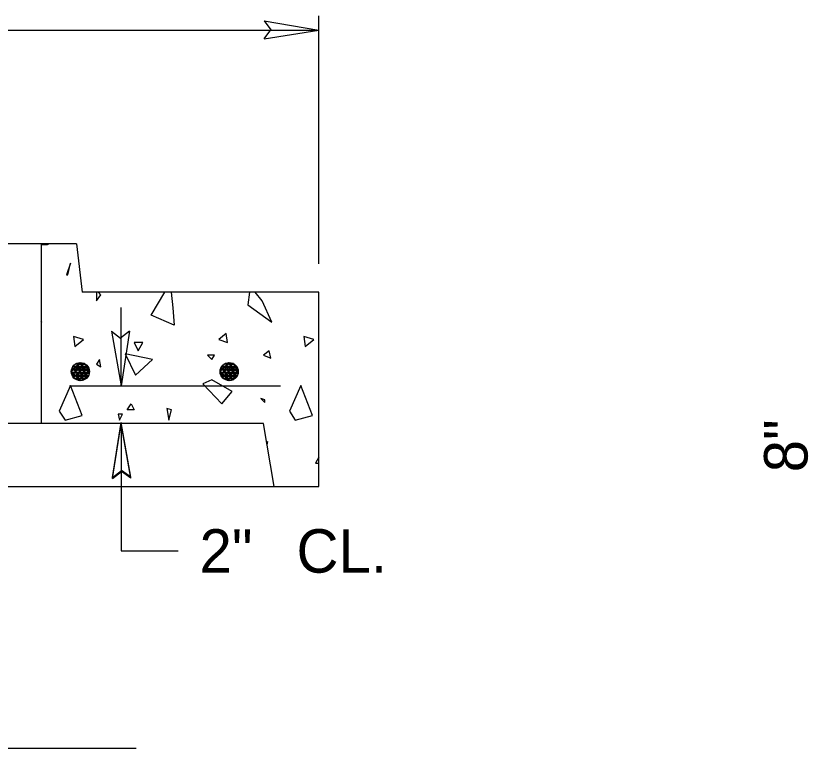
# Model space of a CAD drawing. Extents: x 26.41 to 33.74, y 20.66 to 30.6.
# Drawn here: x 30.528 to 31.62, y 27.311 to 28.321 of the extents above; entities that cross this region are included whole.
import ezdxf

# ---------------------------------------------------------------- set-up
doc = ezdxf.new("R2010")
doc.units = 0
for name, color, linetype in [('DETL-DIMS', 7, 'Continuous'), ('DETL-LINE', 7, 'Continuous'), ('DETL-NOTE', 7, 'Continuous'), ('DETL-PATT', 7, 'Continuous'), ('DETL-TITL', 7, 'Continuous')]:
    doc.layers.add(name, color=color, linetype=linetype)

msp = doc.modelspace()

# ---------------------------------------------------------------- linework, layer by layer
at = {"layer": 'DETL-DIMS'}
for p, q in [((30.8701, 28.3146), (30.9456, 28.3017)), ((30.8701, 28.3146), (30.8795, 28.302)), ((30.9456, 27.9792), (30.9456, 28.3214)), ((29.3909, 28.3017), (30.9456, 28.3017)), ((30.87, 28.2894), (30.8795, 28.302)), ((30.87, 28.2894), (30.9456, 28.3017)), ((30.6731, 27.8108), (30.6731, 27.9189)), ((30.6594, 27.8861), (30.6731, 27.8108)), ((30.6594, 27.8861), (30.6721, 27.8768)), ((30.6846, 27.8864), (30.6721, 27.8768)), ((30.6846, 27.8864), (30.6731, 27.8108)), ((30.6611, 27.6845), (30.6729, 27.7601)), ((30.6611, 27.6832), (30.6729, 27.7588)), ((30.6863, 27.6847), (30.6729, 27.7601)), ((30.6729, 27.7601), (30.6729, 27.5831)), ((30.6863, 27.6835), (30.6729, 27.7588)), ((30.6611, 27.6845), (30.6736, 27.694)), ((30.6611, 27.6832), (30.6736, 27.6928)), ((30.6863, 27.6847), (30.6736, 27.694)), ((30.6863, 27.6835), (30.6736, 27.6928)), ((30.6729, 27.5831), (30.7515, 27.5831))]:
    msp.add_line(p, q, dxfattribs=at)
at = {"layer": 'DETL-LINE'}
for p, q in [((30.6113, 28.0069), (29.4803, 28.0069)), ((30.5628, 28.0069), (30.5628, 27.7588)), ((30.6113, 28.0069), (30.6193, 27.9399)), ((30.9456, 27.9399), (30.6193, 27.9399)), ((30.9456, 27.6721), (30.9456, 27.9399)), ((30.606, 27.8351), (30.6151, 27.8255)), ((30.6157, 27.8365), (30.6062, 27.8273)), ((30.6158, 27.8423), (30.6063, 27.8332)), ((30.6163, 27.8421), (30.6067, 27.8329)), ((30.6162, 27.8362), (30.6067, 27.827)), ((30.6206, 27.8363), (30.6073, 27.8365)), ((30.6205, 27.8333), (30.6073, 27.8336)), ((30.6206, 27.8375), (30.6074, 27.8377)), ((30.6089, 27.8379), (30.6181, 27.8284)), ((30.6186, 27.8336), (30.6091, 27.8244)), ((30.6187, 27.8394), (30.6092, 27.8302)), ((30.6192, 27.8391), (30.6096, 27.8299)), ((30.6247, 27.8333), (30.6114, 27.8335)), ((30.6247, 27.8374), (30.6115, 27.8376)), ((30.6247, 27.8362), (30.6115, 27.8364)), ((30.6118, 27.8349), (30.621, 27.8254)), ((30.6119, 27.8408), (30.621, 27.8313)), ((30.6216, 27.8364), (30.612, 27.8272)), ((30.622, 27.8361), (30.6124, 27.8269)), ((30.6147, 27.8378), (30.6239, 27.8283)), ((30.6244, 27.8335), (30.6149, 27.8243)), ((30.6245, 27.8393), (30.615, 27.8301)), ((30.625, 27.839), (30.6154, 27.8298)), ((30.6288, 27.8332), (30.6155, 27.8334)), ((30.6176, 27.8349), (30.6268, 27.8253)), ((30.6177, 27.8406), (30.6269, 27.8311)), ((30.6274, 27.8363), (30.6179, 27.8271)), ((30.6278, 27.836), (30.6183, 27.8268)), ((30.8111, 27.8351), (30.8203, 27.8255)), ((30.8209, 27.8365), (30.8114, 27.8273)), ((30.821, 27.8423), (30.8115, 27.8332)), ((30.8214, 27.8362), (30.8118, 27.827)), ((30.8215, 27.8421), (30.8119, 27.8329)), ((30.8258, 27.8375), (30.8125, 27.8377)), ((30.8258, 27.8363), (30.8125, 27.8365)), ((30.8257, 27.8333), (30.8125, 27.8336)), ((30.8141, 27.8379), (30.8233, 27.8284)), ((30.8238, 27.8336), (30.8142, 27.8244)), ((30.8239, 27.8394), (30.8144, 27.8302)), ((30.8243, 27.8391), (30.8148, 27.8299)), ((30.8299, 27.8362), (30.8166, 27.8364)), ((30.8298, 27.8333), (30.8166, 27.8335)), ((30.8299, 27.8374), (30.8167, 27.8376)), ((30.8169, 27.8349), (30.8261, 27.8254)), ((30.8171, 27.8408), (30.8262, 27.8313)), ((30.8267, 27.8364), (30.8172, 27.8272)), ((30.8272, 27.8361), (30.8176, 27.8269)), ((30.8199, 27.8378), (30.8291, 27.8283)), ((30.8296, 27.8335), (30.8201, 27.8243)), ((30.8297, 27.8393), (30.8202, 27.8301)), ((30.8302, 27.839), (30.8206, 27.8298)), ((30.834, 27.8332), (30.8207, 27.8334)), ((30.8228, 27.8349), (30.832, 27.8253)), ((30.8229, 27.8406), (30.8321, 27.8311)), ((30.8326, 27.8363), (30.823, 27.8271)), ((30.833, 27.836), (30.8235, 27.8268)), ((30.6058, 27.8292), (30.615, 27.8197)), ((30.6204, 27.8251), (30.6071, 27.8253)), ((30.6203, 27.8239), (30.6071, 27.8241)), ((30.6205, 27.8292), (30.6072, 27.8294)), ((30.6204, 27.828), (30.6072, 27.8283)), ((30.6205, 27.8322), (30.6073, 27.8324)), ((30.6088, 27.8321), (30.618, 27.8225)), ((30.619, 27.8333), (30.6095, 27.8241)), ((30.6245, 27.8238), (30.6112, 27.8241)), ((30.6246, 27.8291), (30.6113, 27.8294)), ((30.6245, 27.828), (30.6113, 27.8282)), ((30.6245, 27.825), (30.6113, 27.8252)), ((30.6246, 27.8321), (30.6114, 27.8323)), ((30.6117, 27.8291), (30.6209, 27.8196)), ((30.6215, 27.8306), (30.6119, 27.8214)), ((30.6219, 27.8303), (30.6124, 27.8211)), ((30.6146, 27.832), (30.6238, 27.8224)), ((30.6244, 27.8276), (30.6148, 27.8184)), ((30.6247, 27.8273), (30.6152, 27.8181)), ((30.6249, 27.8331), (30.6153, 27.8239)), ((30.6287, 27.8279), (30.6154, 27.8281)), ((30.6288, 27.832), (30.6155, 27.8322)), ((30.6287, 27.8291), (30.6155, 27.8293)), ((30.6273, 27.8305), (30.6177, 27.8213)), ((30.6277, 27.8302), (30.6182, 27.821)), ((30.811, 27.8292), (30.8202, 27.8197)), ((30.8256, 27.828), (30.8123, 27.8283)), ((30.8256, 27.8251), (30.8123, 27.8253)), ((30.8255, 27.8239), (30.8123, 27.8241)), ((30.8257, 27.8322), (30.8124, 27.8324)), ((30.8256, 27.8292), (30.8124, 27.8294)), ((30.814, 27.8321), (30.8232, 27.8225)), ((30.8242, 27.8333), (30.8147, 27.8241)), ((30.8297, 27.825), (30.8164, 27.8252)), ((30.8296, 27.8238), (30.8164, 27.8241)), ((30.8298, 27.8291), (30.8165, 27.8294)), ((30.8297, 27.828), (30.8165, 27.8282)), ((30.8298, 27.8321), (30.8166, 27.8323)), ((30.8168, 27.8291), (30.826, 27.8196)), ((30.8267, 27.8306), (30.8171, 27.8214)), ((30.8271, 27.8303), (30.8175, 27.8211)), ((30.8198, 27.832), (30.829, 27.8224)), ((30.8295, 27.8276), (30.82, 27.8184)), ((30.8299, 27.8273), (30.8204, 27.8181)), ((30.83, 27.8331), (30.8205, 27.8239)), ((30.8339, 27.8291), (30.8206, 27.8293)), ((30.8338, 27.8279), (30.8206, 27.8281)), ((30.8339, 27.832), (30.8207, 27.8322)), ((30.8325, 27.8305), (30.8229, 27.8213)), ((30.8329, 27.8302), (30.8234, 27.821)), ((30.6244, 27.8209), (30.6112, 27.8211)), ((30.8296, 27.8209), (30.8164, 27.8211)), ((30.6019, 27.8108), (30.8927, 27.8108)), ((30.8691, 27.7588), (29.4662, 27.7588)), ((30.884, 27.6721), (30.8691, 27.7588)), ((29.3909, 27.6721), (30.9456, 27.6721))]:
    msp.add_line(p, q, dxfattribs=at)
for points in [[(30.6133, 27.8392), (30.6042, 27.8305)], [(30.6103, 27.8363), (30.6042, 27.8305)], [(30.6074, 27.8335), (30.6042, 27.8305)], [(30.6129, 27.8395), (30.6043, 27.8312)], [(30.6099, 27.8366), (30.6043, 27.8312)], [(30.6069, 27.8338), (30.6043, 27.8312)], [(30.6164, 27.8334), (30.6047, 27.8336)], [(30.6123, 27.8335), (30.6047, 27.8336)], [(30.6082, 27.8335), (30.6047, 27.8336)], [(30.6128, 27.8337), (30.605, 27.8262)], [(30.6132, 27.8333), (30.6052, 27.8257)], [(30.6054, 27.8357), (30.6122, 27.8285)], [(30.6164, 27.8364), (30.6058, 27.8366)], [(30.6123, 27.8364), (30.6058, 27.8366)], [(30.6082, 27.8365), (30.6058, 27.8366)], [(30.6165, 27.8375), (30.6065, 27.8377)], [(30.6124, 27.8376), (30.6065, 27.8377)], [(30.6082, 27.8377), (30.6065, 27.8377)], [(30.6077, 27.8391), (30.6152, 27.8314)], [(30.6164, 27.8429), (30.6093, 27.836)], [(30.6207, 27.8404), (30.6095, 27.8406)], [(30.6165, 27.8405), (30.6095, 27.8406)], [(30.6124, 27.8406), (30.6095, 27.8406)], [(30.6172, 27.8429), (30.6097, 27.8357)], [(30.6111, 27.8416), (30.6182, 27.8342)], [(30.6207, 27.8416), (30.6113, 27.8417)], [(30.6166, 27.8416), (30.6113, 27.8417)], [(30.6124, 27.8417), (30.6113, 27.8417)], [(30.6243, 27.8403), (30.6115, 27.8406)], [(30.6225, 27.8416), (30.6116, 27.8417)], [(30.6214, 27.842), (30.6122, 27.8331)], [(30.6164, 27.8429), (30.6123, 27.8389)], [(30.622, 27.8418), (30.6126, 27.8328)], [(30.6172, 27.8429), (30.6127, 27.8386)], [(30.6214, 27.842), (30.6152, 27.8359)], [(30.622, 27.8418), (30.6155, 27.8356)], [(30.6156, 27.8429), (30.6212, 27.8371)], [(30.6156, 27.8429), (30.624, 27.8341)], [(30.6271, 27.8373), (30.6156, 27.8375)], [(30.6278, 27.8361), (30.6156, 27.8364)], [(30.6225, 27.8416), (30.6157, 27.8417)], [(30.6243, 27.8403), (30.6157, 27.8405)], [(30.625, 27.8397), (30.618, 27.8329)], [(30.6254, 27.8394), (30.6184, 27.8327)], [(30.6278, 27.8361), (30.6197, 27.8363)], [(30.6289, 27.8332), (30.6197, 27.8333)], [(30.6225, 27.8416), (30.6198, 27.8416)], [(30.6243, 27.8403), (30.6198, 27.8404)], [(30.6271, 27.8373), (30.6198, 27.8375)], [(30.6206, 27.8377), (30.629, 27.8289)], [(30.6276, 27.8365), (30.6209, 27.83)], [(30.6278, 27.836), (30.6213, 27.8297)], [(30.6228, 27.8414), (30.6242, 27.8399)], [(30.6228, 27.8414), (30.627, 27.837)], [(30.6228, 27.8414), (30.6278, 27.8361)], [(30.6234, 27.8348), (30.629, 27.8289)], [(30.6236, 27.8406), (30.6278, 27.8361)], [(30.6264, 27.8376), (30.6278, 27.8361)], [(30.818, 27.8395), (30.8094, 27.8312)], [(30.8185, 27.8392), (30.8094, 27.8305)], [(30.8151, 27.8366), (30.8094, 27.8312)], [(30.8155, 27.8363), (30.8094, 27.8305)], [(30.8121, 27.8338), (30.8094, 27.8312)], [(30.8125, 27.8335), (30.8094, 27.8305)], [(30.8216, 27.8334), (30.8098, 27.8336)], [(30.8175, 27.8335), (30.8098, 27.8336)], [(30.8133, 27.8335), (30.8098, 27.8336)], [(30.8179, 27.8337), (30.8101, 27.8262)], [(30.8184, 27.8333), (30.8104, 27.8257)], [(30.8105, 27.8357), (30.8174, 27.8285)], [(30.8216, 27.8364), (30.811, 27.8366)], [(30.8175, 27.8364), (30.811, 27.8366)], [(30.8134, 27.8365), (30.811, 27.8366)], [(30.8217, 27.8375), (30.8117, 27.8377)], [(30.8175, 27.8376), (30.8117, 27.8377)], [(30.8134, 27.8377), (30.8117, 27.8377)], [(30.8129, 27.8391), (30.8204, 27.8314)], [(30.8216, 27.8429), (30.8145, 27.836)], [(30.8258, 27.8404), (30.8146, 27.8406)], [(30.8217, 27.8405), (30.8146, 27.8406)], [(30.8176, 27.8406), (30.8146, 27.8406)], [(30.8223, 27.8429), (30.8149, 27.8357)], [(30.8162, 27.8416), (30.8234, 27.8342)], [(30.8258, 27.8416), (30.8165, 27.8417)], [(30.8217, 27.8416), (30.8165, 27.8417)], [(30.8176, 27.8417), (30.8165, 27.8417)], [(30.8295, 27.8403), (30.8167, 27.8406)], [(30.8276, 27.8416), (30.8168, 27.8417)], [(30.8266, 27.842), (30.8173, 27.8331)], [(30.8216, 27.8429), (30.8175, 27.8389)], [(30.8271, 27.8418), (30.8177, 27.8328)], [(30.8223, 27.8429), (30.8179, 27.8386)], [(30.8266, 27.842), (30.8203, 27.8359)], [(30.8271, 27.8418), (30.8207, 27.8356)], [(30.8208, 27.8429), (30.8263, 27.8371)], [(30.8208, 27.8429), (30.8292, 27.8341)], [(30.8295, 27.8403), (30.8208, 27.8405)], [(30.8323, 27.8373), (30.8208, 27.8375)], [(30.833, 27.8361), (30.8208, 27.8364)], [(30.8276, 27.8416), (30.8209, 27.8417)], [(30.8302, 27.8397), (30.8232, 27.8329)], [(30.8306, 27.8394), (30.8236, 27.8327)], [(30.834, 27.8332), (30.8248, 27.8333)], [(30.8323, 27.8373), (30.8249, 27.8375)], [(30.833, 27.8361), (30.8249, 27.8363)], [(30.8276, 27.8416), (30.825, 27.8416)], [(30.8295, 27.8403), (30.825, 27.8404)], [(30.8258, 27.8377), (30.8342, 27.8289)], [(30.8328, 27.8365), (30.826, 27.83)], [(30.833, 27.836), (30.8265, 27.8297)], [(30.828, 27.8414), (30.8293, 27.8399)], [(30.828, 27.8414), (30.8322, 27.837)], [(30.828, 27.8414), (30.833, 27.8361)], [(30.8286, 27.8348), (30.8342, 27.8289)], [(30.8287, 27.8406), (30.833, 27.8361)], [(30.8316, 27.8376), (30.833, 27.8361)], [(30.6042, 27.8309), (30.6093, 27.8256)], [(30.6042, 27.8309), (30.6121, 27.8226)], [(30.6044, 27.8306), (30.6042, 27.8305)], [(30.6163, 27.8293), (30.6043, 27.8295)], [(30.6122, 27.8294), (30.6043, 27.8295)], [(30.6081, 27.8294), (30.6043, 27.8295)], [(30.6164, 27.8322), (30.6044, 27.8324)], [(30.6122, 27.8323), (30.6044, 27.8324)], [(30.6081, 27.8324), (30.6044, 27.8324)], [(30.6163, 27.8281), (30.6044, 27.8283)], [(30.6122, 27.8282), (30.6044, 27.8283)], [(30.608, 27.8283), (30.6044, 27.8283)], [(30.6098, 27.8308), (30.605, 27.8262)], [(30.6068, 27.828), (30.605, 27.8262)], [(30.6102, 27.8305), (30.6052, 27.8257)], [(30.6073, 27.8276), (30.6052, 27.8257)], [(30.6163, 27.8252), (30.6053, 27.8254)], [(30.6121, 27.8252), (30.6053, 27.8254)], [(30.608, 27.8253), (30.6053, 27.8254)], [(30.6162, 27.824), (30.606, 27.8242)], [(30.6121, 27.8241), (30.606, 27.8242)], [(30.608, 27.8241), (30.606, 27.8242)], [(30.6156, 27.8307), (30.6071, 27.8225)], [(30.6126, 27.8278), (30.6071, 27.8225)], [(30.6097, 27.825), (30.6071, 27.8225)], [(30.6161, 27.8304), (30.6074, 27.8221)], [(30.6131, 27.8276), (30.6074, 27.8221)], [(30.6101, 27.8247), (30.6074, 27.8221)], [(30.6087, 27.8263), (30.6166, 27.818)], [(30.6185, 27.8277), (30.6103, 27.8198)], [(30.6155, 27.8248), (30.6103, 27.8198)], [(30.6189, 27.8274), (30.6108, 27.8195)], [(30.6159, 27.8246), (30.6108, 27.8195)], [(30.6116, 27.8233), (30.6166, 27.818)], [(30.6145, 27.8261), (30.6214, 27.819)], [(30.6214, 27.8247), (30.6145, 27.8182)], [(30.6218, 27.8245), (30.6152, 27.8181)], [(30.6272, 27.8238), (30.6153, 27.824)], [(30.6278, 27.8249), (30.6154, 27.8252)], [(30.6174, 27.8232), (30.6214, 27.819)], [(30.6175, 27.829), (30.625, 27.8212)], [(30.6278, 27.8249), (30.6195, 27.8251)], [(30.6272, 27.8238), (30.6195, 27.8239)], [(30.6291, 27.832), (30.6196, 27.8322)], [(30.6291, 27.8291), (30.6196, 27.8292)], [(30.6289, 27.8279), (30.6196, 27.828)], [(30.6203, 27.826), (30.625, 27.8212)], [(30.6205, 27.8319), (30.6276, 27.8245)], [(30.629, 27.8321), (30.6207, 27.8242)], [(30.6282, 27.8256), (30.6211, 27.8188)], [(30.6272, 27.8246), (30.6211, 27.8188)], [(30.6291, 27.8315), (30.6212, 27.8239)], [(30.6275, 27.8242), (30.6225, 27.8195)], [(30.6275, 27.8242), (30.6225, 27.8195)], [(30.6232, 27.823), (30.625, 27.8212)], [(30.6233, 27.8289), (30.6276, 27.8245)], [(30.6282, 27.8256), (30.6236, 27.8212)], [(30.629, 27.8321), (30.6237, 27.827)], [(30.6275, 27.8242), (30.624, 27.8209)], [(30.6291, 27.8315), (30.6242, 27.8267)], [(30.6262, 27.8259), (30.6276, 27.8245)], [(30.6263, 27.8318), (30.629, 27.8289)], [(30.6282, 27.8256), (30.6266, 27.8241)], [(30.6275, 27.8242), (30.627, 27.8237)], [(30.8094, 27.8309), (30.8144, 27.8256)], [(30.8094, 27.8309), (30.8173, 27.8226)], [(30.8096, 27.8306), (30.8094, 27.8305)], [(30.8215, 27.8293), (30.8094, 27.8295)], [(30.8174, 27.8294), (30.8094, 27.8295)], [(30.8133, 27.8294), (30.8094, 27.8295)], [(30.8215, 27.8322), (30.8096, 27.8324)], [(30.8174, 27.8323), (30.8096, 27.8324)], [(30.8133, 27.8324), (30.8096, 27.8324)], [(30.8215, 27.8281), (30.8096, 27.8283)], [(30.8173, 27.8282), (30.8096, 27.8283)], [(30.8132, 27.8283), (30.8096, 27.8283)], [(30.8149, 27.8308), (30.8101, 27.8262)], [(30.812, 27.828), (30.8101, 27.8262)], [(30.8154, 27.8305), (30.8104, 27.8257)], [(30.8124, 27.8276), (30.8104, 27.8257)], [(30.8214, 27.8252), (30.8105, 27.8254)], [(30.8173, 27.8252), (30.8105, 27.8254)], [(30.8132, 27.8253), (30.8105, 27.8254)], [(30.8214, 27.824), (30.8111, 27.8242)], [(30.8173, 27.8241), (30.8111, 27.8242)], [(30.8131, 27.8241), (30.8111, 27.8242)], [(30.8208, 27.8307), (30.8123, 27.8225)], [(30.8178, 27.8278), (30.8123, 27.8225)], [(30.8149, 27.825), (30.8123, 27.8225)], [(30.8212, 27.8304), (30.8126, 27.8221)], [(30.8182, 27.8276), (30.8126, 27.8221)], [(30.8153, 27.8247), (30.8126, 27.8221)], [(30.8139, 27.8263), (30.8218, 27.818)], [(30.8237, 27.8277), (30.8155, 27.8198)], [(30.8207, 27.8248), (30.8155, 27.8198)], [(30.8241, 27.8274), (30.8159, 27.8195)], [(30.8211, 27.8246), (30.8159, 27.8195)], [(30.8168, 27.8233), (30.8218, 27.818)], [(30.8197, 27.8261), (30.8266, 27.819)], [(30.8265, 27.8247), (30.8197, 27.8182)], [(30.827, 27.8245), (30.8204, 27.8181)], [(30.8324, 27.8238), (30.8205, 27.824)], [(30.833, 27.8249), (30.8206, 27.8252)], [(30.8226, 27.829), (30.8302, 27.8212)], [(30.8226, 27.8232), (30.8266, 27.819)], [(30.834, 27.8279), (30.8247, 27.828)], [(30.833, 27.8249), (30.8247, 27.8251)], [(30.8324, 27.8238), (30.8247, 27.8239)], [(30.8342, 27.832), (30.8248, 27.8322)], [(30.8342, 27.8291), (30.8248, 27.8292)], [(30.8255, 27.826), (30.8302, 27.8212)], [(30.8256, 27.8319), (30.8328, 27.8245)], [(30.8342, 27.8321), (30.8259, 27.8242)], [(30.8343, 27.8315), (30.8263, 27.8239)], [(30.8333, 27.8256), (30.8263, 27.8188)], [(30.8324, 27.8246), (30.8263, 27.8188)], [(30.8327, 27.8242), (30.8277, 27.8195)], [(30.8327, 27.8242), (30.8277, 27.8195)], [(30.8284, 27.823), (30.8302, 27.8212)], [(30.8285, 27.8289), (30.8328, 27.8245)], [(30.8333, 27.8256), (30.8288, 27.8212)], [(30.8342, 27.8321), (30.8289, 27.827)], [(30.8327, 27.8242), (30.8292, 27.8209)], [(30.8343, 27.8315), (30.8293, 27.8267)], [(30.8314, 27.8259), (30.8328, 27.8245)], [(30.8315, 27.8318), (30.8342, 27.8289)], [(30.8333, 27.8256), (30.8318, 27.8241)], [(30.8327, 27.8242), (30.8322, 27.8237)], [(30.6203, 27.821), (30.6084, 27.8212)], [(30.6162, 27.821), (30.6084, 27.8212)], [(30.612, 27.8211), (30.6084, 27.8212)], [(30.6203, 27.8198), (30.61, 27.82)], [(30.6161, 27.8199), (30.61, 27.82)], [(30.612, 27.8199), (30.61, 27.82)], [(30.6125, 27.822), (30.6103, 27.8198)], [(30.613, 27.8217), (30.6108, 27.8195)], [(30.623, 27.8197), (30.6111, 27.8199)], [(30.6144, 27.8203), (30.6166, 27.818)], [(30.6184, 27.8219), (30.6145, 27.8182)], [(30.6154, 27.819), (30.6145, 27.8182)], [(30.6188, 27.8216), (30.6152, 27.8181)], [(30.6159, 27.8187), (30.6152, 27.8181)], [(30.6246, 27.8209), (30.6153, 27.821)], [(30.623, 27.8197), (30.6153, 27.8199)], [(30.6246, 27.8209), (30.6194, 27.821)], [(30.623, 27.8197), (30.6194, 27.8198)], [(30.6203, 27.8202), (30.6214, 27.819)], [(30.6242, 27.8218), (30.6211, 27.8188)], [(30.6212, 27.8189), (30.6211, 27.8188)], [(30.6246, 27.8215), (30.6225, 27.8195)], [(30.8255, 27.821), (30.8136, 27.8212)], [(30.8214, 27.821), (30.8136, 27.8212)], [(30.8172, 27.8211), (30.8136, 27.8212)], [(30.8254, 27.8198), (30.8152, 27.82)], [(30.8213, 27.8199), (30.8152, 27.82)], [(30.8172, 27.8199), (30.8152, 27.82)], [(30.8177, 27.822), (30.8155, 27.8198)], [(30.8182, 27.8217), (30.8159, 27.8195)], [(30.8281, 27.8197), (30.8163, 27.8199)], [(30.8196, 27.8203), (30.8218, 27.818)], [(30.8236, 27.8219), (30.8197, 27.8182)], [(30.8206, 27.819), (30.8197, 27.8182)], [(30.824, 27.8216), (30.8204, 27.8181)], [(30.8281, 27.8197), (30.8204, 27.8199)], [(30.821, 27.8187), (30.8204, 27.8181)], [(30.8298, 27.8209), (30.8205, 27.821)], [(30.8298, 27.8209), (30.8246, 27.821)], [(30.8281, 27.8197), (30.8246, 27.8198)], [(30.8254, 27.8202), (30.8266, 27.819)], [(30.8294, 27.8218), (30.8263, 27.8188)], [(30.8264, 27.8189), (30.8263, 27.8188)], [(30.8298, 27.8215), (30.8277, 27.8195)]]:
    msp.add_lwpolyline(points, dxfattribs=at)
for centre in [(30.6167, 27.8305), (30.8219, 27.8305)]:
    msp.add_circle(centre, 0.0125, dxfattribs=at)
at = {"layer": 'DETL-PATT'}
for points in [[(30.5628, 28.0057), (30.5715, 28.0057), (30.5731, 28.0069)], [(30.639, 27.9399), (30.639, 27.9283), (30.6451, 27.9363), (30.6415, 27.9399)], [(30.7418, 27.9399), (30.7442, 27.9184), (30.746, 27.8948), (30.7144, 27.9085), (30.733, 27.9399)], [(30.85, 27.9399), (30.8474, 27.9226), (30.8809, 27.8986), (30.8673, 27.9283), (30.8579, 27.9399)], [(30.5628, 27.8991), (30.5635, 27.8986), (30.5628, 27.9001)], [(30.8742, 27.7294), (30.8753, 27.734), (30.8737, 27.7325)], [(30.9456, 27.7125), (30.9408, 27.7043), (30.9456, 27.7043)]]:
    msp.add_lwpolyline(points, dxfattribs=at)
for points in [[(30.5975, 27.9641), (30.5994, 27.9641), (30.6031, 27.9802)], [(30.6074, 27.8788), (30.6093, 27.8651), (30.621, 27.875)], [(30.8177, 27.883), (30.8078, 27.875), (30.8196, 27.8708)], [(30.9248, 27.8788), (30.9267, 27.8651), (30.9385, 27.875)], [(30.6909, 27.8708), (30.6965, 27.859), (30.7026, 27.8708)], [(30.6786, 27.8552), (30.6927, 27.8255), (30.7163, 27.8472)], [(30.8691, 27.8533), (30.8791, 27.8491), (30.8772, 27.859)], [(30.639, 27.841), (30.6451, 27.8373), (30.6432, 27.8472)], [(30.7918, 27.8533), (30.7979, 27.8472), (30.8017, 27.8533)], [(30.7857, 27.8137), (30.8116, 27.7859), (30.8258, 27.8033), (30.7979, 27.8193)], [(30.5956, 27.7637), (30.6192, 27.7698), (30.6031, 27.8113), (30.5876, 27.776)], [(30.913, 27.7637), (30.9366, 27.7698), (30.9206, 27.8113), (30.905, 27.776)], [(30.871, 27.7915), (30.8654, 27.7934), (30.871, 27.7877)], [(30.6866, 27.7859), (30.6909, 27.7778), (30.681, 27.7778)], [(30.7361, 27.7797), (30.7385, 27.7637), (30.7423, 27.7778)], [(30.6687, 27.7717), (30.6706, 27.7637), (30.6748, 27.7717)]]:
    msp.add_lwpolyline(points, close=True, dxfattribs=at)
at = {"layer": 'DETL-TITL'}
msp.add_line((29.6428, 27.311), (30.6936, 27.311), dxfattribs=at)

# ---------------------------------------------------------------- texts
at = {"layer": 'DETL-NOTE'}
msp.add_text('8"', height=0.05998, rotation=90, dxfattribs=at).set_placement((31.6193, 27.6916))
for s, p in [('2"', (30.781, 27.5531)), ('CL.', (30.9147, 27.5531))]:
    msp.add_text(s, height=0.05998, dxfattribs=at).set_placement(p)

doc.saveas('drawing.dxf')
